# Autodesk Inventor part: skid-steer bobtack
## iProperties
Author: vincent molino
Shininess: 100.0
Angle Display Precision: 2
Document Length Units: 11272
Document Angle Units: 11286
Document Time Units: 11279
Document Mass Units: 11290
Document Length Units Precision: 3
Document Angle Units Precision: 2
Compacted: True
PropertySet Name: _Private Model Information
Created: 2002-01
Part Number: skid-steer bobtack
Document SubType Name: Modeling
Designer: vincent molino
Control State: 0
Master: False
Checked Out: False
PropertySet Name: Design Tracking Control
Density: 0.0
Volumn: 0.0
Area: 0.0
PropertySet Name: Model Information
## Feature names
1. Extrusion1
2. Extrusion2
3. Extrusion3
4. Extrusion4
5. Fillet1
6. Fillet2
7. Extrusion5
8. Extrusion6
9. Fillet3
10. Fillet4
